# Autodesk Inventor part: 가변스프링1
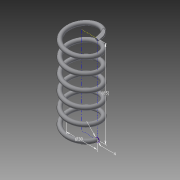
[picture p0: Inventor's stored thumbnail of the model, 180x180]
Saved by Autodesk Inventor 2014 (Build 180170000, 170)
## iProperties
Created: 2017-03
Part Number: 가변스프링1
Material: 강철, 탄소
Document SubType Name: Modeling
Designer: SEC
Density: 1 g/cm^3
Appearance: 반연마
Mass: 7.0356 g
Surface Area: 71.3493 cm^2
Volume: 7.0356 cm^3
Author: SEC
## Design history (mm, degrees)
sketch "스케치1"
  geometry: L1 (0, 0)-(15, 0); L2 (15, 0)-(15, 84.368); L3 (15, 84.368)-(0, 84.368); L4 (0, 84.368)-(0, 0); C1 r 2 at (15, 0)
  constraints: 8 end point, 2 parallel, 1 centre point, 1 coincident, 1 horizontal, 1 perpendicular
  dimensions: "d0" = 30 diameter of L2 L4; "d1" = 84.36759 distance of L1.end L2.end (derived); "d2" = 4 diameter of C1
feature "코일1" pitch "d3" = 10; turns "d5" = 6; dims "d4" = 84.36759 (= d1), "d6" = 0, angle "d7" = 90 deg, angle "d8" = 90 deg, "d9" = 0, "d10" = 0
sketch "스케치2"
  geometry: L1 (-13, 0)-(-17, 0) reference; 1 further point
  constraints: 1 horizontal alignment
extrude "돌출1" cut sketch "스케치2" stored distance "d11" = 10; taper "d12" = 0 deg
node "작업 평면1"
sketch "스케치3"
  geometry: L1 (-2, 0)-(2, 0) reference; 1 further point
  constraints: 1 horizontal alignment
extrude "돌출2" cut sketch "스케치3" stored distance "d13" = 10; taper "d14" = 0 deg
node "솔리드1"
node "절단 모서리 투영1"
node "절단 모서리 투영2"
